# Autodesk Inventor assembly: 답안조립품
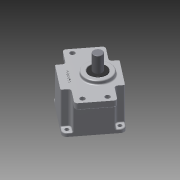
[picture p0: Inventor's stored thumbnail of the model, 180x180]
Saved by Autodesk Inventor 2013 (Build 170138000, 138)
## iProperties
Created: 2015-07
Part Number: 답안조립품
Document SubType Name: Assembly
Designer: user
Author: user
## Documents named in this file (12)
- C:\Users\user\Desktop\450734V1027\답안조립품.iam
- C:\Users\user\Desktop\450734V1027\메인축.ipt
- C:\Users\user\Desktop\450734V1027\베어링 608.ipt
- 베어링 608.ipt
- C:\Users\user\Desktop\450734V1027\서브축.ipt
- C:\Users\user\Desktop\450734V1027\베어링 6003.ipt
- 베어링 6003.ipt
- C:\Users\user\Desktop\450734V1027\본체.ipt
- C:\Users\user\Desktop\450734V1027\커버.ipt
- C:\Users\user\Desktop\450734V1027\M4x0.5x16.ipt
- C:\Users\user\Desktop\450734V1027\오일실 8x22x7.ipt
- C:\Users\user\Desktop\450734V1027\오일실 17x32x8.ipt
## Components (4 placed, 1 different names)
1. M4x0.5x12:1
2. M4x0.5x12:2
3. M4x0.5x12:3
4. M4x0.5x12:4
